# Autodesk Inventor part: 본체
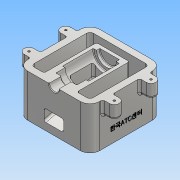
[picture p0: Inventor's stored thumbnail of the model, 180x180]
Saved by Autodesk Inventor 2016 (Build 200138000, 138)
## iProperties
Created: 2018-01
Part Number: 본체
Material: 알루미늄 6061
Document SubType Name: Modeling
Designer: Administrator
Density: 2.7 g/cm^3
Appearance: 알루미늄 - 평지
Mass: 995.308 g
Surface Area: 834.575 cm^2
Volume: 368.633 cm^3
Author: Administrator
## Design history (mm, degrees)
sketch "스케치1"
  geometry: L1 (-55, -55)-(55, -55); L2 (55, -55)-(55, 55); L3 (55, 55)-(-55, 55); L4 (-55, 55)-(-55, -55); L5 (-55, -55)-(55, 55); L6 (55, -55)-(-55, 55); 1 further point
  constraints: 12 end point, 2 midpoint, 2 parallel, 1 horizontal, 1 perpendicular
  dimensions: "d0" = 110 distance of L1.start L1.end; "d1" = 110 distance of L1.end L2.end
extrude "돌출1" new body sketch "스케치1" distance "d2" = 65; taper "d3" = 0 deg
fillet "모깎기1" dims "d4" = 15
feature "쉘1" dims "d5" = 10
sketch "스케치2"
  geometry: L1 (-40, -55)-(40, -55) reference; L2 (-55, 40)-(-55, -40) reference; L3 (-55, -35.5)-(-65, -35.5); L4 (-65, -35.5)-(-65, -20.5); L5 (-65, -20.5)-(-55, -20.5); L6 (-55, -20.5)-(-55, -35.5); A1 r 7.5 centre (-65, -28) between (-65, -20.5) and (-65, -35.5); 1 further point
  constraints: 8 end point, 2 parallel, 2 point on circle, 1 centre point, 1 horizontal, 1 midpoint, 1 perpendicular, 1 point on line
  dimensions: "d6" = 27 distance from line of L1 A1.centre; "d7" = 10 distance of L3.start L3.end; "d8" = 7.5 radius of A1
extrude "돌출2" join sketch "스케치2" distance "d9" = 20; taper "d10" = 0 deg
sketch "스케치4"
  geometry: L1 (-40, 65)-(40, 65) reference; L2 (35, 65)-(35, 30); L3 (35, 30)-(-45, 8.564); L4 (-45, 0)-(-45, 65) reference; L5 (55, 65)-(55, 0) reference; L6 (40, 0)-(-40, 0) reference; L7 (-45, 65)-(35, 65); L8 (-40, 65)-(-40, 0) reference; 1 further point
  constraints: 6 end point, 2 point on line, 1 perpendicular, 1 vertical
  dimensions: "d13" = 20 distance between parallel lines of L5 L2; "d14" = 105 deg angle of L4 L3; "d15" = 30 distance from line of L6 L2.end
extrude "돌출3" join sketch "스케치4" stored distance "d16" = 50; taper "d17" = 0 deg
sketch "스케치6"
  geometry: L1 (-55, 65)-(-40, 65) reference; L2 (40, 65)-(55, 65) reference; L3 (-55, 65)-(30, 65); L4 (-55, 72.5)-(-36, 72.5); L5 (-36, 72.5)-(-36, 81); L6 (-36, 81)-(-22, 81); L7 (-22, 81)-(-22, 85); L8 (-22, 85)-(25, 85); L9 (25, 85)-(25, 80); L10 (25, 80)-(30, 80); L11 (30, 80)-(30, 65); L12 (-55, 0)-(-55, 65) reference; L13 (-55, 72.5)-(-55, 65); 1 further point
  constraints: 20 end point, 7 perpendicular, 2 horizontal, 1 vertical
  dimensions: "d20" = 15 diameter of L4 L3; "d21" = 32 diameter of L6 L3; "d22" = 40 diameter of L8 L3; "d24" = 30 diameter of L10 L3; "d25" = 19 distance of L4.start L4.end; "d26" = 14 distance of L5.end L6.end; "d27" = 47 distance of L7.end L8.end; "d28" = 5 distance of L9.end L10.end
revolve "회전1" sketch "스케치6" stored, may be unused: angle "d29" = 90 deg
sketch "스케치9"
  geometry: L1 (20, 65)-(20, 31.157); L2 (35, 65)-(35, 30); L3 (35, 30)-(-45, 8.564); L4 (-45, 65)-(35, 65); L5 (-55, 11.061)-(20, 31.157); L6 (-55, 0)-(-55, 65) reference; L7 (-55, 29.061)-(-17, 39.243); L8 (-17, 39.243)-(-17, 65); L9 (20.5, 65)-(-20.5, 65) reference; L10 (-17, 65)-(20, 65); L11 (-55, 29.061)-(-55, 11.061); L12 (-22, 65)-(-22, 49) reference; 1 further point
  constraints: 12 end point, 3 point on line, 2 vertical, 1 collinear, 1 horizontal, 1 parallel
  dimensions: "d37" = 5 distance between parallel lines of L3 L5; "d38" = 18 distance of L5.start L7.start; "d39" = 37 distance between parallel lines of L1 L8; "d71" = 5 distance between parallel lines of L12 L8
extrude "돌출4" cut sketch "스케치9" stored distance "d40" = 30; taper "d41" = 0 deg
hole "구멍1" diameter "d44" = 3.242; stored, may be unused: countersink angle "d48" = 90 deg, drill point angle "d50" = 118 deg; dims "d42" = 10, "d43" = 10, "d45" = 9, "d46" = 4, "d47" = 2, "d49" = 11
fillet "모깎기2" dims "d51" = 1
chamfer "모따기2" distance "d52" = 1; stored, may be unused: second distance "d53" = 2, angle "d54" = 45 deg
fillet "모깎기3" dims "d55" = 3
fillet "모깎기4" dims "d56" = 3
fillet "모깎기5" dims "d57" = 3
fillet "모깎기6" dims "d58" = 3
fillet "모깎기7" dims "d59" = 3
fillet "모깎기8" dims "d60" = 3
fillet "모깎기9" dims "d61" = 3
sketch "스케치11"
  geometry: L1 (0, 0)-(0, 80) reference; L2 (-65, -15)-(0, -15) reference; 2 further points
  constraints: 1 other
  dimensions: "d66" = 20 distance from line of L1 point (-20, 40); "d67" = 55 distance from line of L2 point (-20, 40)
feature "엠보싱2" sketch "스케치11" dims "d0" = 110, "d1" = 110, "d6" = 27, "d7" = 10, "d8" = 7.5, "d68" = 0.5, "d69" = 0
node "솔리드1"
mirror "대칭1"
mirror "대칭2"
mirror "대칭3"
mirror "대칭4"
